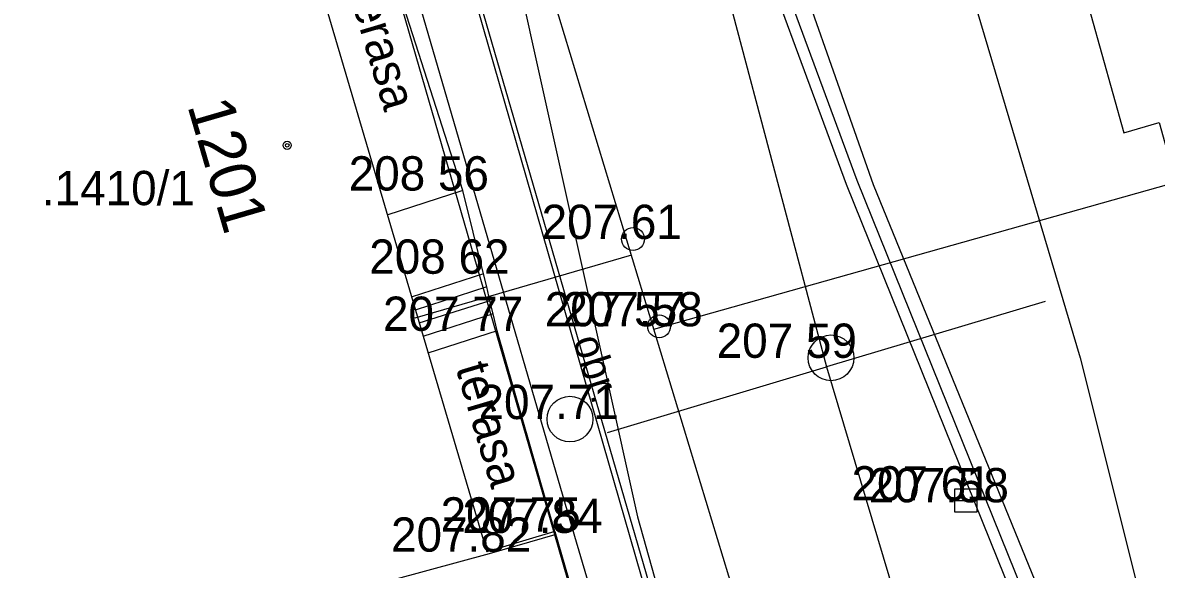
# Model space of a CAD drawing. Extents: x -524633 to -524336, y -1187893 to -1187683.
# Drawn here: x -524519.98 to -524495.18, y -1187799.22 to -1187787.26 of the extents above; entities that cross this region are included whole.
import ezdxf

# ---------------------------------------------------------------- set-up
doc = ezdxf.new("R2010")
doc.units = 0
for name, color, linetype in [('Hranice parcel', 7, 'Continuous'), ('Parcelní čísla', 7, 'Continuous'), ('Vrstva 1', 7, 'Continuous'), ('Vrstva 10', 7, 'Continuous'), ('Vrstva 11', 7, 'Continuous'), ('Vrstva 27', 7, 'Continuous'), ('Vrstva 28', 7, 'Continuous'), ('Vrstva 3', 7, 'Continuous'), ('Vrstva 39', 7, 'Continuous'), ('Vrstva 4', 7, 'Continuous'), ('Vrstva 40', 7, 'Continuous'), ('Vrstva 41', 7, 'Continuous'), ('Vrstva 47', 7, 'Continuous'), ('Vrstva 5', 7, 'Continuous'), ('Vrstva 52', 7, 'Continuous'), ('Vrstva 53', 7, 'Continuous'), ('Vrstva 54', 7, 'Continuous'), ('Vrstva 55', 7, 'Continuous')]:
    doc.layers.add(name, color=color, linetype=linetype)

msp = doc.modelspace()

# ---------------------------------------------------------------- linework, layer by layer
at = {"layer": 'Hranice parcel'}
msp.add_line((-524504.56, -1187811.45), (-524508.34, -1187798.46), dxfattribs=at)
for points in [[(-524492.87, -1187767.16), (-524493.09, -1187767.53), (-524492.5, -1187767.9), (-524493.08, -1187768.83), (-524492.92, -1187769.39), (-524499.12, -1187771.13), (-524496.96, -1187778.81), (-524498.79, -1187779.32), (-524499.35, -1187780.04), (-524499.38, -1187780.95), (-524498.86, -1187781.65), (-524498.06, -1187781.92), (-524495.89, -1187789.67), (-524495.12, -1187789.44), (-524494.64, -1187791.17), (-524493.58, -1187790.87), (-524492.28, -1187795.49), (-524491.56, -1187795.29), (-524491.29, -1187796.25), (-524489.17, -1187795.65), (-524487.55, -1187796.64), (-524480.71, -1187794.88), (-524477.19, -1187807.33)], [(-524504.01, -1187770.49), (-524496.85, -1187794.59), (-524491.95, -1187814.16)], [(-524508.34, -1187798.46), (-524508.82, -1187796.8), (-524512.95, -1187782.56)], [(-524508.34, -1187798.46), (-524509.78, -1187798.88), (-524518.07, -1187801.13)]]:
    msp.add_lwpolyline(points, dxfattribs=at)
at = {"layer": 'Vrstva 1'}
for p, q in [((-524510.35, -1187790.93), (-524510.35, -1187790.93)), ((-524506.63, -1187791.99), (-524506.63, -1187791.99)), ((-524509.9, -1187792.75), (-524509.9, -1187792.75)), ((-524509.6, -1187794), (-524509.6, -1187794)), ((-524506.08, -1187793.9), (-524506.08, -1187793.9)), ((-524506.06, -1187793.9), (-524506.06, -1187793.9)), ((-524502.3, -1187794.59), (-524502.3, -1187794.59)), ((-524508.01, -1187795.93), (-524508.01, -1187795.93)), ((-524499.38, -1187797.75), (-524499.38, -1187797.75)), ((-524499.35, -1187797.71), (-524499.35, -1187797.71)), ((-524508.34, -1187798.39), (-524508.34, -1187798.39)), ((-524508.27, -1187798.42), (-524508.27, -1187798.42)), ((-524509.83, -1187798.83), (-524509.83, -1187798.83))]:
    msp.add_line(p, q, dxfattribs=at)
at = {"layer": 'Vrstva 10'}
msp.add_lwpolyline([(-524505.229, -1187803.87), (-524505.079, -1187803.84), (-524505.369, -1187802.63), (-524510.679, -1187784.37), (-524510.92, -1187783.49)], dxfattribs=at)
at = {"layer": 'Vrstva 11'}
for p, q in [((-524510.35, -1187790.93), (-524512.27, -1187784.96)), ((-524510.35, -1187790.93), (-524512.016, -1187791.466)), ((-524509.9, -1187792.75), (-524510.35, -1187790.93)), ((-524509.9, -1187792.75), (-524511.483, -1187793.262)), ((-524509.83, -1187793.04), (-524511.399, -1187793.544)), ((-524509.76, -1187793.34), (-524511.314, -1187793.832)), ((-524509.69, -1187793.63), (-524511.228, -1187794.12)), ((-524509.6, -1187794), (-524511.118, -1187794.49))]:
    msp.add_line(p, q, dxfattribs=at)
for points in [[(-524505.229, -1187803.87), (-524505.495, -1187802.663), (-524510.75, -1187784.44), (-524511.045, -1187783.524)], [(-524509.6, -1187794), (-524509.69, -1187793.63), (-524509.76, -1187793.34), (-524509.83, -1187793.04), (-524509.9, -1187792.75)], [(-524508.339, -1187798.39), (-524509.6, -1187794)]]:
    msp.add_lwpolyline(points, dxfattribs=at)
at = {"layer": 'Vrstva 27'}
msp.add_line((-524499.6, -1187797.71), (-524499.1, -1187797.71), dxfattribs=at)
msp.add_lwpolyline([(-524499.6, -1187797.96), (-524499.1, -1187797.96), (-524499.1, -1187797.46), (-524499.6, -1187797.46)], close=True, dxfattribs=at)
for centre in [(-524502.299, -1187794.59), (-524508.01, -1187795.93)]:
    msp.add_circle(centre, 0.5, dxfattribs=at)
at = {"layer": 'Vrstva 28'}
for centre in [(-524506.63, -1187791.99), (-524506.059, -1187793.9)]:
    msp.add_circle(centre, 0.25, dxfattribs=at)
at = {"layer": 'Vrstva 39'}
for radius in [0.09, 0.0398]:
    msp.add_circle((-524514.196, -1187789.941), radius, dxfattribs=at)
at = {"layer": 'Vrstva 5'}
msp.add_line((-524508.339, -1187798.39), (-524509.829, -1187798.83), dxfattribs=at)
for points in [[(-524514.699, -1187782.43), (-524514.66, -1187782.561), (-524514.53, -1187782.89), (-524509.83, -1187798.83)], [(-524508.339, -1187798.39), (-524506.539, -1187804.6)]]:
    msp.add_lwpolyline(points, dxfattribs=at)
at = {"layer": 'Vrstva 52'}
for points in [[(-524496.398, -1187840.378), (-524494.948, -1187840.08), (-524494.688, -1187839.875), (-524487.612, -1187837.45), (-524481.715, -1187835.492), (-524481.43, -1187834.708), (-524482.034, -1187831.222), (-524482.934, -1187828.39), (-524483.247, -1187825.883), (-524485.431, -1187819.747), (-524488.09, -1187813.944), (-524489.77, -1187814.215), (-524492.275, -1187815.202), (-524493.527, -1187813.248), (-524494.448, -1187809.538), (-524497.926, -1187800.125), (-524501.727, -1187790.707), (-524504.173, -1187784.072), (-524504.862, -1187780.152), (-524505.655, -1187777.244), (-524505.315, -1187776.503)], [(-524486.932, -1187812.511), (-524487.392, -1187812.716), (-524488.246, -1187813.711), (-524489.008, -1187813.544), (-524492.116, -1187814.721), (-524492.941, -1187813.226), (-524495.729, -1187804.887), (-524497.543, -1187800.186), (-524501.372, -1187790.808), (-524503.625, -1187784.398), (-524504.544, -1187780.063), (-524504.509, -1187778.639), (-524505.44, -1187777.03), (-524505.101, -1187776.436)], [(-524483.491, -1187825.944), (-524485.662, -1187819.843), (-524488.238, -1187814.221), (-524489.704, -1187814.458), (-524492.375, -1187815.51), (-524493.76, -1187813.348), (-524494.687, -1187809.612), (-524498.159, -1187800.215), (-524501.96, -1187790.797), (-524504.415, -1187784.139), (-524505.106, -1187780.207), (-524505.87, -1187777.458), (-524505.484, -1187776.552)]]:
    msp.add_lwpolyline(points, dxfattribs=at)
at = {"layer": 'Vrstva 53'}
for points in [[(-524525.446, -1187746.167), (-524511.928, -1187773.746), (-524506.531, -1187798.067), (-524502.9, -1187810.999), (-524500.825, -1187817.931), (-524498.784, -1187825.686)], [(-524518.67, -1187775.66), (-524515.01, -1187774.04), (-524512.56, -1187782.53), (-524507.91, -1187798.49), (-524506.24, -1187804.15), (-524505.21, -1187807.9), (-524504.64, -1187809.64)]]:
    msp.add_lwpolyline(points, dxfattribs=at)
at = {"layer": 'Vrstva 54'}
for p, q in [((-524488.745, -1187851.342), (-524510.722, -1187778.991)), ((-524506.175, -1187793.961), (-524494.102, -1187790.565)), ((-524506.666, -1187792.344), (-524511.407, -1187793.723))]:
    msp.add_line(p, q, dxfattribs=at)
at = {"layer": 'Vrstva 55'}
for p, q in [((-524510.39, -1187764.59), (-524502.4, -1187794.79)), ((-524497.61, -1187793.356), (-524502.4, -1187794.79)), ((-524507.19, -1187796.224), (-524502.4, -1187794.79)), ((-524502.4, -1187794.79), (-524497.74, -1187810.36))]:
    msp.add_line(p, q, dxfattribs=at)

# ---------------------------------------------------------------- texts
at = {"layer": 'Parcelní čísla'}
msp.add_text('.1410/1', height=0.75, dxfattribs=at).set_placement((-524519.562, -1187791.25))
at = {"layer": 'Vrstva 3'}
for s, p in [('208 56 ', (-524512.85, -1187790.93)), ('207.61', (-524508.63, -1187791.99)), ('207 57 ', (-524508.56, -1187793.9)), ('207 59 ', (-524504.8, -1187794.59)), ('207.71', (-524510.01, -1187795.93)), ('207.58', (-524501.474, -1187797.75))]:
    msp.add_text(s, height=0.75, dxfattribs=at).set_placement(p)
at = {"layer": 'Vrstva 4'}
for s, p in [('208 62 ', (-524512.4, -1187792.75)), ('207.58', (-524508.174, -1187793.9)), ('207 77 ', (-524512.1, -1187794)), ('207 61 ', (-524501.85, -1187797.71)), ('207 75 ', (-524510.84, -1187798.39)), ('207.84', (-524510.364, -1187798.42)), ('207.82', (-524511.924, -1187798.83))]:
    msp.add_text(s, height=0.75, dxfattribs=at).set_placement(p)
at = {"layer": 'Vrstva 40'}
msp.add_text('obr.', height=0.65, rotation=287.4555, dxfattribs=at).set_placement((-524507.946, -1187794.205))
at = {"layer": 'Vrstva 41'}
for p in [(-524512.859, -1187786.556), (-524510.515, -1187794.808)]:
    msp.add_text('terasa', height=0.75, rotation=286.5358, dxfattribs=at).set_placement(p)
at = {"layer": 'Vrstva 47'}
msp.add_text('1201', height=1, rotation=286.26, dxfattribs=at).set_placement((-524516.386, -1187789.069))

doc.saveas('drawing.dxf')
